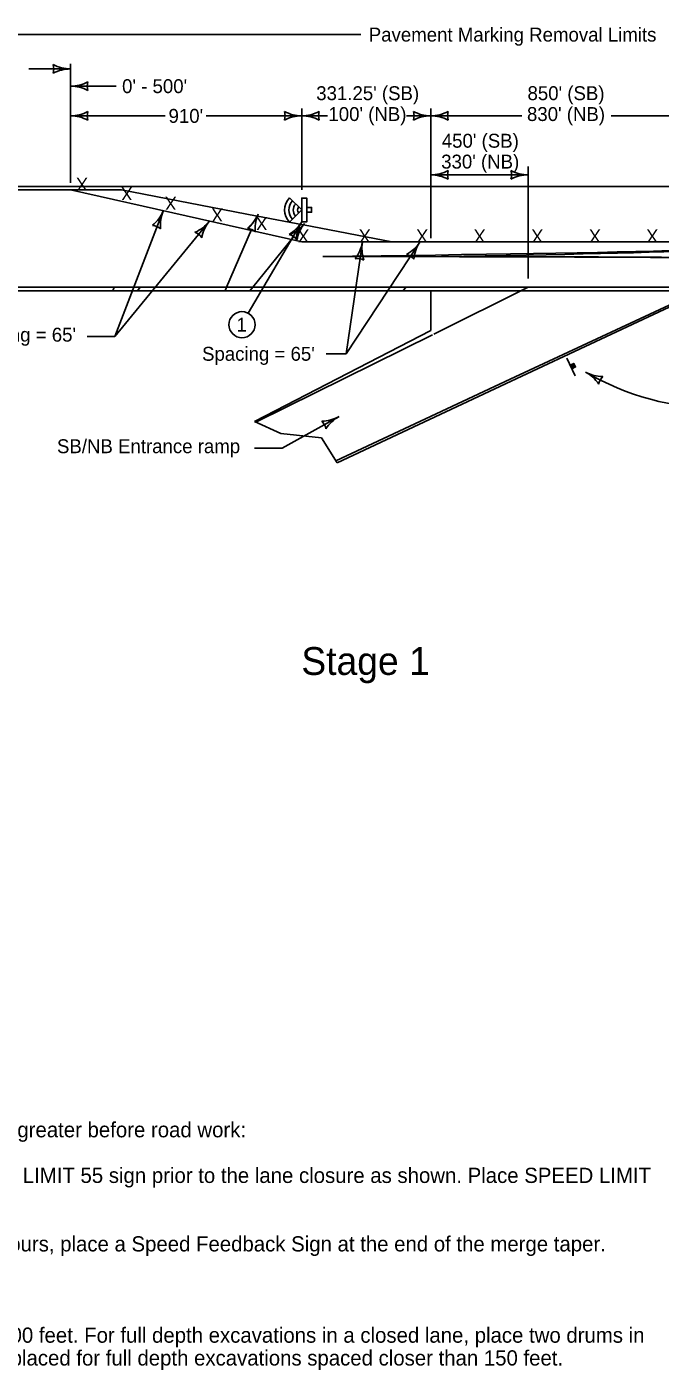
# Model space of a CAD drawing. Extents: x 10134 to 13311, y 7934 to 9733.
# Drawn here: x 11309 to 12036, y 8001 to 9547 of the extents above; entities that cross this region are included whole.
import ezdxf

# ---------------------------------------------------------------- set-up
doc = ezdxf.new("R2010")
doc.units = 0
for name, color, linetype in [('dsnCellElements', 7, 'Continuous'), ('dsnNonPlotable', 7, 'Continuous'), ('dsnStdBlock', 7, 'Continuous'), ('dsnstdModifiedBlock', 7, 'Continuous'), ('dsnStdNote', 7, 'Continuous'), ('dsnStdShading', 7, 'Continuous'), ('SheetText', 7, 'Continuous')]:
    doc.layers.add(name, color=color, linetype=linetype)

msp = doc.modelspace()

# ---------------------------------------------------------------- linework, layer by layer
at = {"layer": 'dsnCellElements'}
msp.add_line((11630.3, 9349.7), (11630.3, 9322.2), dxfattribs=at)
for points in [[(11624.6, 9322.2), (11624.6, 9349.7), (11630.3, 9349.7), (11630.3, 9322.2)], [(11630.3, 9333.3), (11630.3, 9338.9), (11635.9, 9338.9), (11635.9, 9333.3)]]:
    msp.add_lwpolyline(points, close=True, dxfattribs=at)
at = {"layer": 'dsnNonPlotable'}
for p, q in [((11610.5, 9350.1), (11624.6, 9336)), ((11630.3, 9349.7), (11624.6, 9349.7)), ((11624.6, 9336), (11610.5, 9321.8)), ((11630.3, 9322.2), (11624.6, 9322.2)), ((11929.3, 9165.5), (11938.8, 9145.3)), ((11935.3, 9153.6), (11933.3, 9157.7)), ((11933.5, 9157.8), (11935.5, 9153.7)), ((11935.7, 9153.7), (11933.7, 9157.9)), ((11933.9, 9157.9), (11935.8, 9153.8)), ((11936, 9153.9), (11934.1, 9158)), ((11934.2, 9158.1), (11936.2, 9154)), ((11936.4, 9154.1), (11934.5, 9158.2)), ((11934.7, 9158.3), (11936.6, 9154.2)), ((11936.8, 9154.3), (11934.8, 9158.4)), ((11935.1, 9158.5), (11937, 9154.4)), ((11937.3, 9154.5), (11935.4, 9158.6)), ((11935.7, 9158.8), (11937.6, 9154.7)), ((11937.8, 9154.7), (11935.8, 9158.8)), ((11936.1, 9159), (11938.1, 9154.9)), ((11938.2, 9155), (11936.3, 9159.1)), ((11936.5, 9159.2), (11938.5, 9155.1)), ((11938.6, 9155.1), (11936.7, 9159.3)), ((11936.9, 9159.4), (11938.9, 9155.3))]:
    msp.add_line(p, q, dxfattribs=at)
msp.add_lwpolyline([(11935, 9153.4), (11933.1, 9157.6), (11937.2, 9159.5), (11939.2, 9155.4)], close=True, dxfattribs=at)
for radius, start, end in [(20.3, 135.88, 224.0313), (15.3, 136.1665, 223.7159), (10.3, 136.7294, 223.0963), (5.32, 138.7005, 221.2995)]:
    msp.add_arc((11625.1, 9335.9), radius, start, end, dxfattribs=at)
at = {"layer": 'dsnstdModifiedBlock'}
for p, q in [((10162.6, 9359), (11358.9, 9359)), ((11358.9, 9359), (11624.6, 9299.3)), ((11624.6, 9299.3), (12282.4, 9299.3)), ((10154.7, 9247), (11772.8, 9247)), ((11772.8, 9247), (11884.9, 9247)), ((11884.9, 9247), (11776.2, 9193.1)), ((11774.7, 9192.4), (11572.7, 9092.3))]:
    msp.add_line(p, q, dxfattribs=at)
msp.add_lwpolyline([(11663.8, 9047.2), (11864.1, 9141.4), (12091.2, 9247)], dxfattribs=at)
at = {"layer": 'dsnStdNote'}
msp.add_circle((11555.9, 9204), 15, dxfattribs=at)
at = {"layer": 'dsnStdShading'}
for p, q in [((12420.3, 9363), (11205.9, 9363)), ((11417.3, 9359), (11205.9, 9359)), ((11205.9, 9359), (11417.3, 9359)), ((11573.4, 9329), (11417.3, 9359)), ((11417.3, 9359), (11573.4, 9329)), ((11573.6, 9329), (11626.3, 9318.8)), ((11626.3, 9318.8), (11573.6, 9329)), ((11626.4, 9318.8), (11728, 9299.3)), ((11728, 9299.3), (11626.4, 9318.8)), ((11538.2, 9247), (11566.8, 9313.6)), ((11566.8, 9313.6), (11538.2, 9247)), ((11568.2, 9247), (11615.5, 9305.4)), ((11615.5, 9305.4), (11568.2, 9247)), ((11728, 9299.3), (12256.6, 9299.3)), ((12289.4, 9299.3), (11728, 9299.3)), ((11538.2, 9247), (10154.7, 9247)), ((10158.7, 9243), (11565, 9243)), ((10158.7, 9243), (11536.5, 9243)), ((10989.4, 9247), (11538.2, 9247)), ((11408.9, 9247), (11407.3, 9243)), ((11407.3, 9243), (11435.9, 9243)), ((11439, 9247), (11408.9, 9247)), ((11435.9, 9243), (11439, 9247)), ((11536.5, 9243), (11538.2, 9247)), ((11538.2, 9247), (11536.5, 9243)), ((11536.5, 9243), (11565, 9243)), ((11568.2, 9247), (11538.2, 9247)), ((11538.2, 9247), (11568.2, 9247)), ((11568.2, 9247), (11565, 9243)), ((11565, 9243), (11568.2, 9247)), ((11565, 9243), (12214.7, 9243)), ((12217.7, 9247), (11568.2, 9247)), ((11744.1, 9247), (11741.2, 9243)), ((11741.2, 9243), (12291.2, 9243)), ((12296.3, 9247), (11744.1, 9247)), ((11772.8, 9197.5), (11772.8, 9243)), ((11772.8, 9243), (12086.8, 9243)), ((12086.8, 9243), (11865.2, 9139.2)), ((11570.4, 9092.5), (11772.8, 9197.5)), ((11865.2, 9139.2), (11665.1, 9045.2)), ((11600.5, 9078.9), (11570.4, 9092.5)), ((11647.4, 9073.9), (11600.5, 9078.9)), ((11665.1, 9045.2), (11647.4, 9073.9))]:
    msp.add_line(p, q, dxfattribs=at)
for points in [[(11574.1, 9330.3), (11574.4, 9331.2), (11574.4, 9331.2)], [(11574.1, 9330.3), (11574.1, 9330.3)], [(11626.4, 9318.8), (11626.3, 9318.8)], [(11627.2, 9319.8), (11627.6, 9320.3), (11627.6, 9320.3)], [(11568.2, 9247), (12287.3, 9247), (12285.3, 9247)]]:
    msp.add_lwpolyline(points, dxfattribs=at)
for centre, radius, start, end in [((11535.2, 9347.6), 42.5, 309.2655, 336.072), ((11535.2, 9347.6), 42.5, 309.2655, 334.0959), ((11613.6, 9314.8), 42.5, 160.5422, 185.4105), ((11613.6, 9314.8), 42.5, 160.5422, 185.4105), ((11535.2, 9347.6), 42.5, 334.0959, 336.072), ((11613.6, 9314.8), 42.5, 157.3556, 160.5422), ((11613.6, 9314.8), 42.5, 158.6034, 160.5422), ((11535.2, 9347.6), 42.5, 337.3204, 337.338), ((11594.3, 9346.8), 42.5, 293.3393, 318.8219), ((11594.3, 9346.8), 42.5, 293.3393, 318.8219), ((11660.8, 9293.8), 42.5, 143.9415, 169.4842), ((11660.8, 9293.8), 42.5, 143.9415, 169.4842), ((11594.3, 9346.8), 42.5, 318.8219, 320.5615), ((11660.8, 9293.8), 42.5, 141.4294, 143.9415), ((11594.3, 9346.8), 42.5, 321.3942, 321.4118), ((11560.7, 9298.3), 16.4, 68.0792, 85.0713), ((11560.7, 9298.3), 16.4, 49.6046, 85.0713), ((11560.7, 9298.3), 16.4, 49.6046, 68.0792), ((11605.3, 9292.5), 16.4, 51.9095, 69.1451), ((11605.3, 9292.5), 16.4, 33.6784, 69.1451), ((11605.3, 9292.5), 16.4, 33.6784, 51.9095)]:
    msp.add_arc(centre, radius, start, end, dxfattribs=at)
for centre, major_axis, ratio, start_param, end_param in [((6684.7, 9331.8), (5526.2, -32.7), 0.008175, 5.82835, 6.279465), ((8654.5, 9315.3), (3556.3, -16.3), 0.011041, 5.788962, 6.278612), ((9235.2, 9266.8), (2972.6, 11.6), 0.003601, 0.004187, 0.623197), ((9969.8, 9266), (2238, 12.4), 0.004792, 0.005553, 0.624564)]:
    msp.add_ellipse(centre, major_axis=major_axis, ratio=ratio, start_param=start_param, end_param=end_param, dxfattribs=at)
at = {"layer": 'SheetText'}
for p, q in [((11692.3, 9537.7), (11215.3, 9537.7)), ((11358.9, 9367.2), (11358.9, 9503.9)), ((11311.1, 9498.3), (11358.9, 9498.3)), ((11411.3, 9478.4), (11358.9, 9478.4)), ((11467.6, 9444.2), (11358.9, 9444.2)), ((11624.6, 9444.3), (11514.6, 9444.3)), ((11624.6, 9359.3), (11624.6, 9452.8)), ((11624.6, 9444.3), (11654.2, 9444.3)), ((11744.8, 9444.3), (11772.8, 9444.3)), ((11772.8, 9303.7), (11772.8, 9452.8)), ((11772.8, 9444.3), (11877.5, 9444.3)), ((11980.1, 9444.3), (12086.8, 9444.3)), ((11884.9, 9257.1), (11884.9, 9386)), ((11800.8, 9376.3), (11772.8, 9376.3)), ((11800.8, 9376.3), (11884.9, 9376.4)), ((11465.4, 9334.8), (11409.9, 9190.3)), ((11518.2, 9322.8), (11409.9, 9190.3)), ((11624.6, 9322.2), (11562.9, 9217.2)), ((11760.2, 9298.9), (11675.8, 9170.5)), ((11694.2, 9298.9), (11675.8, 9170.5)), ((11377.9, 9190.3), (11409.9, 9190.3)), ((11675.8, 9170.5), (11652.7, 9170.5)), ((11667.5, 9098.3), (11602.2, 9062)), ((11570.2, 9062), (11602.2, 9062))]:
    msp.add_line(p, q, dxfattribs=at)
for centre, radius, start, end in [((11323.2, 9498.2), 16.4, 342.2666, 17.7334), ((11358.9, 9540.7), 42.5, 241.9275, 270), ((11358.9, 9455.7), 42.5, 90, 118.0725), ((11358.9, 9520.9), 42.5, 270, 298.0725), ((11358.9, 9435.9), 42.5, 61.9275, 90), ((11394.5, 9478.4), 16.4, 162.2666, 197.7334), ((11358.9, 9486.7), 42.5, 270, 298.0725), ((11358.9, 9401.7), 42.5, 61.9275, 90), ((11394.5, 9444.2), 16.4, 162.2666, 197.7334), ((11589, 9444.3), 16.4, 342.2666, 17.7334), ((11624.6, 9486.8), 42.5, 241.9275, 270), ((11624.6, 9401.8), 42.5, 90, 118.0725), ((11624.6, 9486.8), 42.5, 270, 298.0725), ((11624.6, 9401.8), 42.5, 61.9275, 90), ((11660.3, 9444.3), 16.4, 162.2666, 197.7334), ((11737.2, 9444.3), 16.4, 342.2666, 17.7334), ((11772.8, 9486.8), 42.5, 241.9275, 270), ((11772.8, 9401.8), 42.5, 90, 118.0725), ((11772.8, 9486.8), 42.5, 270, 298.0725), ((11772.8, 9401.8), 42.5, 61.9275, 90), ((11808.5, 9444.3), 16.4, 162.2666, 197.7334), ((11772.8, 9418.8), 42.5, 270, 298.0725), ((11808.5, 9376.3), 16.4, 162.2666, 197.7334), ((11849.3, 9376.4), 16.4, 342.2666, 17.7333), ((11884.9, 9418.9), 42.5, 241.9275, 270), ((11772.8, 9333.8), 42.5, 61.9275, 90), ((11884.9, 9333.9), 42.5, 90, 118.0725), ((11426.2, 9351.2), 42.5, 309.2655, 337.338), ((11504.6, 9318.4), 42.5, 157.338, 185.4105), ((11451.7, 9301.9), 16.4, 49.6046, 85.0713), ((11485, 9349.3), 42.5, 293.3393, 321.4118), ((11551.4, 9296.3), 42.5, 141.4118, 169.4842), ((11588.5, 9344.5), 42.5, 300.2855, 328.358), ((11660.8, 9299.9), 42.5, 148.358, 176.4305), ((11496, 9295), 16.4, 33.6784, 69.1451), ((11606, 9291.9), 16.4, 40.6246, 76.0913), ((11652.3, 9305.8), 42.5, 322.5687, 350.6412), ((11736.2, 9292), 42.5, 170.6412, 198.7137), ((11724.7, 9322.2), 42.5, 298.6127, 326.6852), ((11795.7, 9275.6), 42.5, 146.6852, 174.7577), ((11688.4, 9263.7), 16.4, 62.9079, 98.3746), ((11740.6, 9269.1), 16.4, 38.9518, 74.4185), ((12104.7, 9412.4), 304.7, 239.624, 270.1276), ((11970.8, 9186.9), 42.5, 241.5824, 269.6549), ((11930.4, 9112.1), 42.5, 33.5099, 61.5824), ((11981.9, 9132.5), 16.4, 133.849, 169.3157), ((11646.8, 9135.5), 42.5, 271.0181, 299.0906), ((11636.3, 9081), 16.4, 11.3573, 46.824), ((11688.1, 9061.2), 42.5, 119.0906, 147.1631)]:
    msp.add_arc(centre, radius, start, end, dxfattribs=at)

# ---------------------------------------------------------------- texts
at = {"layer": 'dsnCellElements'}
for p in [(11378.8, 9373.1), (11430.2, 9362.3), (11480.7, 9351.2), (11534.2, 9337.9), (11585.3, 9328), (11633.1, 9313.7), (11703.7, 9313.7), (11769.7, 9313.7), (11835.7, 9313.7), (11902, 9313.7), (11968.2, 9313.8), (12034.1, 9313.8)]:
    msp.add_text('X', height=15, rotation=180, dxfattribs=at).set_placement(p)
at = {"layer": 'dsnStdBlock'}
msp.add_text('Stage 1', height=32, dxfattribs=at).set_placement((11624.1, 8801.1))
at = {"layer": 'dsnStdNote'}
msp.add_text('1', height=16, dxfattribs=at).set_placement((11549.5, 9196))
at = {"layer": 'SheetText'}
for s, height, p in [('Pavement Marking Removal Limits', 16, (11701.6, 9529.7)), ("0' - 500'", 16, (11418.1, 9470.4)), ("331.25' (SB)", 16, (11641.2, 9462.3)), ("850' (SB)", 16, (11884, 9462.3)), ("910'", 16, (11471.5, 9436.2)), ("100' (NB)", 16, (11655.2, 9438.3)), ("830' (NB)", 16, (11883.4, 9438.3)), ("450' (SB)", 16, (11785.5, 9407.6)), ("330' (NB)", 16, (11784.8, 9383.6)), ("Spacing = 65'", 16, (11235.6, 9184.5)), ("Spacing = 65'", 16, (11510, 9162.5)), ('SB/NB Entrance ramp', 16, (11343.3, 9056.2)), ('For roadways with a posted speed limit of 60 mph or greater before road work:', 17.5, (10748.9, 8269.2)), ('Place SPEED LIMIT AHEAD sign and SPEED LIMIT 55 sign prior to the lane closure as shown. Place SPEED LIMIT', 17.5, (10818.9, 8216.7)), ('For traffic control zones lasting more than 4 hours, place a Speed Feedback Sign at the end of the merge taper.', 17.5, (10818.9, 8137.9)), ('For lanes closed to traffic, place two drums every 1000 feet. For full depth excavations in a closed lane, place two drums in ', 17.5, (10748.9, 8032.9)), ('front of each location. Additional drums need not be placed for full depth excavations spaced closer than 150 feet.', 17.5, (10748.9, 8006.7))]:
    msp.add_text(s, height=height, dxfattribs=at).set_placement(p)

doc.saveas('drawing.dxf')
